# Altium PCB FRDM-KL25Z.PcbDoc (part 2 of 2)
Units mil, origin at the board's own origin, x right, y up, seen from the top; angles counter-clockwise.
Board outline 3200 x 2100 mil, 2 copper layers (Top Layer, Bottom Layer), stack 42.17 mil thick; 0 components, 164 nets, 466 pads, 402 vias.
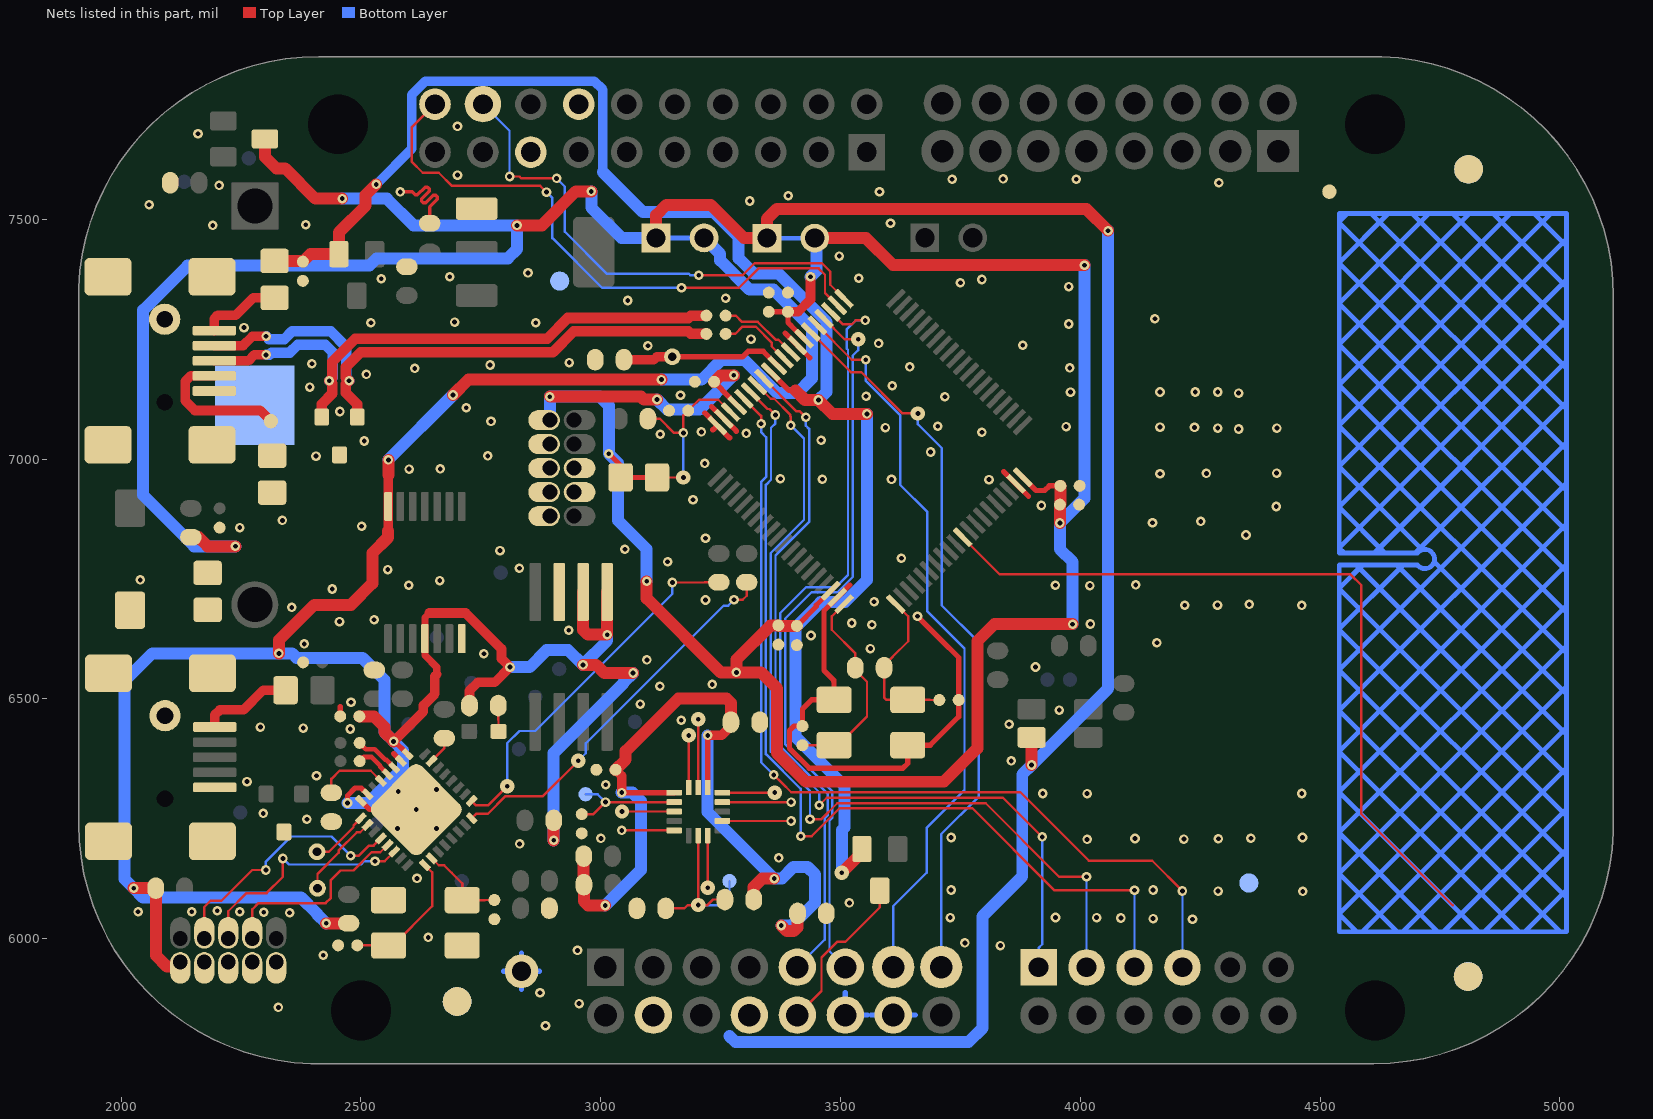
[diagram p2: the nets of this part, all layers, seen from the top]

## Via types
v1: diameter 20/20 (per signal layer), hole 10, Top Layer to Bottom Layer, 372 vias
v2: diameter 20/30 (per signal layer), hole 10, Top Layer to Bottom Layer, 25 vias
v3: diameter 20/30.04 (per signal layer), hole 10, Top Layer to Bottom Layer, 5 vias

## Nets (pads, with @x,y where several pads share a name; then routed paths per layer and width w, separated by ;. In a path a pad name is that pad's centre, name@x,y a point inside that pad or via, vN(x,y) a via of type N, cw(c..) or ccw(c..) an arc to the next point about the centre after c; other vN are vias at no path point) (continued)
$Net110: pad.6@2223.5,6000 pad.14@2569.57,6181.28 | length 486.1
  Top Layer w5: pad.6@2223.5,6001 2223.5,6057 2261.5,6095 2303.5,6095 2337.5,6129 v1(2337.5,6167) ; v1(2529.5,6161.5) 2549.79,6161.5 pad.14@2569.57,6181.28
  Bottom Layer w5: v1(2337.5,6167) 2349.88,6154.62 2359.88,6154.62 2359.97,6154.53 2500.03,6154.53 2507,6161.5 v1(2529.5,6161.5)
$Net111: pad.4@2173.5,6000 pad.12@2541.71,6209.14 | length 535.9
  Top Layer w5: pad.4@2173.5,6001 2173.5,6066 2186.5,6079 2209.5,6079 2273.5,6143 v1(2302,6143) ; v1(2478.5,6173) 2496,6173 2516.94,6193.94 2526.51,6193.94 pad.12@2541.71,6209.14
  Bottom Layer w5: v1(2302,6143) 2302,6160.5 2354.5,6213 2438.5,6213 v1(2478.5,6173)
$Net112: pad.1@2418.5,7087.5 pad.1@3220.5,7299 pad.3@2194.4,7204.8 | length 1279
  Top Layer w20: pad.3@2194.4,7204.8 2265.3,7204.8 2277.5,7217 v1(2302.5,7217)
  Top Layer w22: pad.1@2418.5,7087.5 2418.5,7114.56 2440.5,7136.56 2440.5,7156.48 v1(2433.98,7163) 2440.5,7169.52 2440.5,7203 2488.5,7251 2888.5,7251 2931.5,7294 3183,7294 3188,7299 pad.1@3220.5,7299
  Bottom Layer w22: v1(2302.5,7217) 2309.43,7217 2314.43,7222 2352.1,7222 2368.1,7238 2425.5,7238 2441.06,7222.44 2441.06,7170.08 v1(2433.98,7163)
$Net113: pad.1@2492.5,7087.5 pad.1@3220.5,7261 pad.2@2194.4,7236.3 | length 1283.4
  Top Layer w20: pad.2@2194.4,7236.3 2254.4,7236.3 2274.03,7255.93 v1(2302.5,7255.93)
  Top Layer w22: pad.1@2492.5,7087.5 2492.5,7114.56 2468.5,7138.56 2468.5,7156 v1(2475.5,7163) 2468.5,7170 2468.5,7191.4 2500.1,7223 2900.5,7223 2943.5,7266 3183,7266 3188,7261 pad.1@3220.5,7261
  Bottom Layer w22: v1(2302.5,7255.93) 2308.43,7250 2340.5,7250 2356.5,7266 2437.1,7266 2469.06,7234.04 2469.06,7169.44 v1(2475.5,7163)
$Net114: pad.1@3304.5,6743 pad.24@2731.08,6250.93 | length 805.6
  Top Layer w5: pad.24@2731.08,6250.93 2740.27,6260.12 2764.47,6260.12 2801.55,6297.2 2879.6,6297.2 v2(2953.1,6370.7) ; v1(3278,6706.5) 3296,6706.5 3304.5,6715 pad.1@3304.5,6743
  Bottom Layer w5: v2(2953.1,6370.7) 2969.01,6386.61 2969.01,6407.03 3256.1,6694.12 3265.62,6694.12 v1(3278,6706.5)
$Net115: pad.1@3246.5,6743 pad.25@2731.08,6287.07 | length 778.2
  Top Layer w5: pad.25@2731.08,6287.07 2740.27,6277.88 2765.38,6277.88 v2(2805,6317.5) ; v1(3149.5,6742.5) 3216,6742.5 3216.5,6743 pad.1@3246.5,6743
  Bottom Layer w5: v2(2805,6317.5) 2805,6407.2 2830.8,6433 2863.5,6433 3149.5,6719 v1(3149.5,6742.5)
$Net116: pad.1@2960.5,6259.5 pad.1@2968.5,6301 pad.2@3153.3,6284.69 | length 251.5
  Top Layer w5: pad.1@2960.5,6259.5 2984.85,6259.5 v1(3010.04,6284.69) pad.2@3153.3,6284.69
  Bottom Layer w5: pad.1@2968.5,6301 2993.73,6301 v1(3010.04,6284.69)
$Net117: pad.1@3135.5,6063 pad.1@3259,6081.5 pad.1@3268.5,6120 pad.7@3203.5,6214.8 | length 379.2
  Top Layer w5: pad.1@3135.5,6063 3174.4,6063 3181.4,6070 v2(3203.5,6070) ; pad.7@3203.5,6214.8 v2(3203.5,6070) ; pad.1@3259,6081.5 3234,6081.5 3222.5,6070 v2(3203.5,6070)
  Bottom Layer w5: v2(3203.5,6070) 3248.5,6070 3268.5,6090 pad.1@3268.5,6120
$Net118: pad.1@3223.19,6106.26 pad.8@3223.19,6214.8 | length 108.5
  Top Layer w5: v3(3223.19,6106.26) pad.8@3223.19,6214.8
$Net119: pad.1@3044.5,6265 pad.3@3153.3,6265 | length 108.8
  Top Layer w5: v3(3044.5,6265) pad.3@3153.3,6265
$Net120: pad.1@3183.81,6423.74 pad.16@3183.81,6315.2 | length 108.5
  Top Layer w5: pad.16@3183.81,6315.2 v3(3183.81,6423.74)
$Net121: pad.1@3203.5,6457.4 pad.15@3203.5,6315.2 | length 142.2
  Top Layer w5: pad.15@3203.5,6315.2 v3(3203.5,6457.4)
$Net122: pad.1@3363.11,6304.37 pad.13@3253.7,6304.37 | length 109.4
  Top Layer w5: pad.13@3253.7,6304.37 v3(3363.11,6304.37)
$Net123: pad.1@2409.5,6105 pad.10@2513.85,6237 | length 179.4
  Top Layer w5: pad.1@2409.5,6105 2409.5,6135 2453.5,6179 2453.5,6183.7 2491.6,6221.8 2498.65,6221.8 pad.10@2513.85,6237
$Net124: pad.1@2408.5,6181 pad.9@2499.92,6250.93 | length 122.4
  Top Layer w5: pad.1@2408.5,6181 2433.5,6181 2484.72,6232.22 2484.72,6235.73 pad.9@2499.92,6250.93
$Net126: pad.15@2854.5,7640
$Net127: pad.1@3582,6100.2 pad.12@3410.04,5840.65 | length 340.9
  Top Layer w5: pad.12@3410.04,5840.65 3460.5,5891.11 3460.5,5961 3492.7,5993.2 3510,5993.2 3582,6065.2 pad.1@3582,6100.2
$Net128: pad.1@2091.85,6464.81
$Net129: pad.1@2091.85,6291.59
$Net130: pad.1@2091.05,7291.41
$Net131: pad.1@2091.05,7118.19
$Net132: pad.1@2500,5850
$Net133: pad.1@2452,7698
$Net134: pad.1@4614.5,5850
$Net135: pad.1@4614.5,7698
$Net136: pad.1@2180.5,6685.5 pad.B01@1973.74,6203 pad.B01@1973.74,6553.4 pad.B01@2190.28,6203 pad.B01@2190.28,6553.4
$Net137: pad.1@2315,7007 pad.B01@1972.94,7029.6 pad.B01@1972.94,7380 pad.B01@2189.48,7029.6 pad.B01@2189.48,7380
$Net138: pad.1@2194.4,7267.79 pad.1@2320,7336 | length 168.5
  Top Layer w20: pad.1@2194.4,7267.79 2194.4,7292.79 2201.5,7299.89 2239.39,7299.89 2275.5,7336 pad.1@2320,7336
$Net139: pad.1@2786.5,6486 pad.1@2787.01,6432 | length 54.2
  Top Layer w5: pad.1@2786.5,6486 2786.5,6456 2787.01,6455.49 pad.1@2787.01,6432
$Net140: pad.1@3591,6564.8 pad.1@3640.17,6497.84 pad.1@3706.3,6497.5 pad.41 | length 343.7
  Top Layer w5: pad.41@3615.45,6697.58 3641.26,6671.77 3641.26,6620.16 3608.68,6587.58 3608.68,6587.48 3591,6569.8 pad.1@3591,6564.8 3591,6503.01 3596.17,6497.84 pad.1@3640.17,6497.84 3685.96,6497.84 3686.3,6497.5 pad.1@3706.3,6497.5
$Net141: pad.1@3420.7,6403.3 pad.1@3531,6564.8 pad.3@3486.63,6403.36 pad.40 | length 435.1
  Top Layer w5: pad.1@3420.7,6403.3 3442.57,6403.3 3442.63,6403.36 pad.3@3486.63,6403.36 3495.63,6403.36 3555.3,6463.03 3555.3,6535.5 3531,6559.8 pad.1@3531,6564.8 3531,6594.8 3481.74,6644.06 3481.74,6671.77 pad.40@3507.55,6697.58
$Net142: pad.1@2674.1,6417.9 pad.31@2647.5,6370.65 | length 58.3
  Top Layer w5: pad.31@2647.5,6370.65 2674.1,6397.25 pad.1@2674.1,6417.9
$Net143: pad.1@2195.2,6441.19 pad.1@2343,6518 | length 194.3
  Top Layer w20: pad.1@2195.2,6441.19 2195.2,6466.19 2205.91,6476.9 2255.4,6476.9 2296.5,6518 pad.1@2343,6518
$Net144: pad.1@2711.27,6080.24 pad.1@2778.5,6080.5 pad.18@2647.5,6167.35 | length 187.7
  Top Layer w5: pad.18@2647.5,6167.35 2648.15,6167.35 2662.5,6153 2673.5,6153 2689.5,6137 2711.27,6115.24 pad.1@2711.27,6080.24 2758.24,6080.24 2758.5,6080.5 pad.1@2778.5,6080.5
$Net145: pad.1@2492.5,5986 pad.3@2557.73,5985.76 pad.17@2633.57,6153.42 | length 282.3
  Top Layer w5: pad.1@2492.5,5986 2557.49,5986 pad.3@2557.73,5985.76 2566.73,5985.76 2648.77,6067.8 2648.77,6138.22 pad.17@2633.57,6153.42
$Net146: pad.8@2273.5,6000 pad.13@2555.64,6195.21 | length 419.4
  Top Layer w5: pad.8@2273.5,6001 2273.5,6061 2286.5,6074 2426.5,6074 2437.5,6085 2437.5,6122 2457.5,6142 2484.5,6142 2522.51,6180.01 2540.44,6180.01 pad.13@2555.64,6195.21
$Net147: pad.1@2497.5,6408 pad.3@2569.57,6356.72 | length 93.3
  Top Layer w10: pad.1@2497.5,6408 2510.5,6395 2528.5,6395 2550.5,6373 2553.29,6373 pad.3@2569.57,6356.72
$Net148: pad.1@2497.5,6370 pad.4@2555.64,6342.79 | length 78.3
  Top Layer w10: pad.1@2497.5,6370 2506.5,6379 2521.87,6379 2540.5,6360.37 2540.5,6357.93 pad.4@2555.64,6342.79
$Net151: pad.1@2312.5,7079 pad.4@2194.4,7173.3 | length 302.5
  Top Layer w20: pad.4@2194.4,7173.3 2145,7173.3 2133.5,7161.8 2133.5,7121.62 2153.92,7101.2 2290.3,7101.2 pad.1@2312.5,7079
$Net152: pad.51 | length 1619.1
  Top Layer w5: pad.51@3754.65,6836.77 3831.92,6759.5 4563.2,6759.5 4585.7,6737 4585.7,6260.1 4776.5,6069.3
$Net153: pad.1@2438.5,6304 pad.5@2541.71,6328.86 | length 147.9
  Top Layer w5: pad.1@2438.5,6304 2438.5,6333 2455.4,6349.9 2520.67,6349.9 pad.5@2541.71,6328.86
$Net154: 
$Net155: pad.9@2323.5,5951
$Net156: pad.7@2273.5,5951
$Net157: pad.9@2894,6881
$Net158: pad.8@2944,6931
$Net159: 
$Net160: pad.6@2944,6981
$Net161: 
$Net162: pad.1@2700.7,5868.9
$Net163: pad.1@4808.5,5921
$Net164: pad.1@4809.5,7604
$Net165: 
$Net166: 
$Net167: 
$Net168: 
$Net169: 
$Net170: 
$Net171: 
$Net172: 
$Net173: 
$Net174: pad.7@2894,6931
$Net175: 
$Net176: 
$Net177: pad.1@2700.7,5868.9
$Net178: pad.1@4808.7,5921.1
$Net179: pad.1@4809.5,7604.1
D14: pad.1@2754.5,7740 pad.1@3507.55,7334.42 | length 1068.9
  Top Layer w5: v1(2810,7589) 2830.5,7589 2834.5,7585 v1(2908,7585) ; v1(3204.5,7383) 3296,7383 3321,7408 3461.5,7408 3478.5,7391 3478.5,7363.47 pad.1@3507.55,7334.42
  Bottom Layer w5: pad.1@2754.5,7740 2810,7684.5 v1(2810,7589) ; v1(2908,7585) 2925.3,7567.7 2925.3,7473.7 3013,7386 3184,7386 3187,7383 v1(3204.5,7383)
D15: pad.2@3493.62,7320.5 pad.18@2654.5,7740 | length 1256
  Top Layer w5: pad.18@2654.5,7740 2606.5,7692 2606.5,7619.5 2629,7597 2662.5,7597 2690,7569.5 2874,7569.5 v1(2887,7556.5) ; v1(3168.5,7357) 3288.5,7357 3329,7397.5 3454.5,7397.5 3467.81,7384.19 3467.81,7346.31 pad.2@3493.62,7320.5
  Bottom Layer w5: v1(2887,7556.5) 2899.38,7544.12 2899.38,7460.62 3003,7357 v1(3168.5,7357)
GND: pad.1@2018.5,6684.7 pad.1@2102.5,7576 pad.1@2180.5,6762.5 pad.1@2205.5,6857 pad.1@2279,7111.95 pad.1@2315,6930 pad.1@2339.5,6222.5 pad.1@2379,7371.5 pad.1@2379.5,6576 pad.1@2438.5,6244 pad.1@2452.5,5986 pad.1@2455.5,7008.5 pad.1@2457,6463.5 pad.1@2528,6560 pad.1@2596,7401 pad.1@2615.5,6269 pad.1@2643.5,7491.5 pad.1@2741.45,7522.05 pad.1@2778.5,6040.5 pad.1@2835.1,5932 pad.1@2893,6063.5 pad.1@2914.5,7371 pad.1@2960.5,6219.5 pad.1@2988.5,7207 pad.1@2991,6352 pad.1@3075.5,6063 pad.1@3142.5,7101 pad.1@3196.5,7161 pad.1@3331.5,6451.5 pad.1@3350.5,7347 pad.1@3370.5,6613 pad.1@3390.5,7347 pad.1@3409,6612 pad.1@3420.7,6443.3 pad.1@3470.5,6052.5 pad.1@3746.3,6497.5 pad.1@3997.5,6905 pad.1@3998.5,6944 pad.1@4351.5,6116 pad.1@4519.4,7557.4 pad.2@2557.73,6080.24 pad.2@2583.5,6370.65 pad.2@3486.63,6497.84 pad.3@2173.5,5951 pad.3@2894,7031 pad.4@2711.27,5985.76 pad.4@3640.17,6403.36 pad.5@2194.4,7141.81 pad.5@2195.2,6315.21 pad.5@2223.5,5951 pad.5@2894,6981 pad.5@3153.3,6225.63 pad.7@2710.24,6625.5 pad.7@2913.5,6722.79 pad.8@2499.92,6287.07 pad.8@3410.11,7236.99 pad.10@3253.7,6245.31 pad.12@3253.7,6284.69 pad.14@2954.5,7740 pad.14@3510.04,5840.69 pad.16@3610.04,5840.73 pad.19@3257,7083.88 pad.20@3243.08,7069.95 pad.39 pad.59 | length 30353.5
  Top Layer w5: v1(3043.89,6225.63) pad.5@3153.3,6225.63 ; pad.10@3253.7,6245.31 v1(3396.96,6245.31) ; pad.12@3253.7,6284.69 v1(3396.96,6284.69)
  Top Layer w7: v1(2582,7557) 2607,7557 2613.06,7550.94 2618.02,7550.94 2634.06,7566.98 2639.02,7566.98 2642.55,7563.45 2642.55,7558.49 2626.51,7542.45 2626.51,7537.49 2630.04,7533.96 2635,7533.96 2651.04,7550 2656,7550 2659.53,7546.47 2659.53,7541.51 2643.5,7525.48 pad.1@2643.5,7491.5
  Top Layer w11: pad.1@2457,6463.5 2457,6483.52 ; pad.8@2499.92,6287.07 2518,6269 v1(2615.5,6269) ; 2568.28,6385.87 pad.2@2583.5,6370.65 ; 3217.26,7095.77 pad.20@3243.08,7069.95 ; 3231.18,7109.7 pad.19@3257,7083.88 3282.82,7058.06 ; 3233.87,7060.74 pad.20@3243.08,7069.95 ; 3268.9,7044.13 pad.20@3243.08,7069.95 ; 3384.29,7262.81 pad.8@3410.11,7236.99 3435.93,7211.17 ; 3519.44,6737.32 pad.39@3493.62,6711.5 3465.69,6683.57 3465.69,6559.21 3485.8,6539.1 3485.8,6536.67 3486.63,6535.84 pad.2@3486.63,6497.84 3439.63,6497.84 3420.7,6478.91 pad.1@3420.7,6443.3 3402.9,6443.3 3393.7,6434.1 3393.7,6396.7 3435,6355.4 3630.21,6355.4 3640.17,6365.36 pad.4@3640.17,6403.36 3687.17,6403.36 3746.3,6462.49 pad.1@3746.3,6497.5 3746.3,6521.5 3746.5,6521.7 3746.5,6586.1 3707.6,6625 3707.5,6625 v1(3660.5,6672) ; 3840.18,6973.94 pad.59@3866,6948.12 3891.82,6922.3
  Bottom Layer w10: 4540.01,6050.52 4576.03,6014.5 ; 4540,6051.74 5014,6525.74 ; 4540.01,6135.37 4660.88,6014.5 ; 4540.01,6136.6 5014,6610.59 ; 4540,6220.23 4745.73,6014.5 ; 4540.01,6221.45 5014,6695.44 ; 4540,6305.08 4830.58,6014.5 ; 4540,6306.3 5014,6780.3 ; 4540.01,6389.93 4915.44,6014.5 ; 4540,6391.15 5014,6865.15 ; 4540,6474.79 5000.29,6014.5 ; 4540.01,6476.01 5014,6950 ; 4540,6559.64 5014,6085.64 ; 4540.01,6560.86 5014,7034.85 ; 4540.01,6644.49 5014,6170.5 ; 4540,6645.71 4673.27,6778.98 ; 4540.01,6729.34 5014,6255.35 ; 4540.01,6730.57 4588.42,6778.98 ; 4540,6814.2 4550.18,6804.02 ; 4540.01,6815.42 5014,7289.41 ; 4540,6899.05 4635.03,6804.02 ; 4540,6900.27 5014,7374.27 ; 4540.01,6983.9 4713.12,6810.79 ; 4540,6985.12 5014,7459.12 ; 4540.01,7068.75 5014,6594.76 ; 4540.01,7069.98 4982.03,7512 ; 4540,7153.61 5014,6679.61 ; 4540.01,7154.83 4897.18,7512 ; 4540.01,7238.46 5014,6764.47 ; 4540,7239.68 4812.32,7512 ; 4540.01,7323.31 5014,6849.32 ; 4540.01,7324.54 4727.47,7512 ; 4540,7408.17 5014,6934.17 ; 4540.01,7409.39 4642.62,7512 ; 4540,7493.02 5014,7019.02 ; 4540,7494.24 4557.76,7512 ; 4575.22,6778.98 5014,6340.2 ; 4587.61,6014.5 5014,6440.89 ; 4605.88,7512 5014,7103.88 ; 4613.46,6804.02 5014,7204.56 ; 4660.07,6778.98 5014,6425.05 ; 4672.47,6014.5 5014,6356.03 ; 4690.73,7512 5014,7188.73 ; 4698.32,6804.03 5014,7119.71 ; 4737.79,6786.12 5014,6509.91 ; 4757.32,6014.5 5014,6271.18 ; 4775.58,7512 5014,7273.58 ; 4842.17,6014.5 5014,6186.33 ; 4860.44,7512 5014,7358.44 ; 4927.03,6014.5 5014,6101.47 ; 4945.29,7512 5014,7443.29 ; 5011.88,6014.5 5014,6016.62 ; 4540,6014.5 5014,6014.5 5014,7512 4540,7512 4540,6804.02 4702.87,6804.02 cw(c4718.5,6791.5) 4702.87,6778.98 4540,6778.98 4540,6014.5
  Bottom Layer w11: 2797.58,5932 pad.1@2835.1,5932 ; 2835.1,5894.48 pad.1@2835.1,5932 ; 2835.1,5969.52 pad.1@2835.1,5932 ; 2872.62,5932 pad.1@2835.1,5932 ; 3510.04,5887.21 pad.14@3510.04,5840.69 3556.56,5840.69 ; 3563.52,5840.73 pad.16@3610.04,5840.73 3656.56,5840.73
  other v1: 2885,5818.5 2328,5856.5 2955,5864.5 2873.5,5887 2421.5,5965.5 2951.7,5975.5 3833.5,5985.5 3759.5,5991 2640.5,6002.5 4233.9,6040.3 4151.8,6041.7 4084.7,6043.1 3728.7,6043.8 3948.4,6044.1 4034,6043.8 2351.5,6054 2297.5,6055 2035.5,6056 2147.5,6056 2247.5,6056 2200.5,6058 3518.7,6074.5 4287.3,6099.2 4464,6098.5 3730.7,6101.3 4151.8,6101.3 2617,6125.5 3371.1,6168.4 2831,6197.5 4014.1,6206.8 4216,6207.5 4288,6208.1 3000.5,6209 4114,6208.8 4355.8,6209.4 3730.7,6210.8 4463.3,6210.8 2576.1,6229.7 2657.7,6229.9 2387.5,6249 2296.5,6261 4014.1,6302.3 3921.8,6302.5 4461.9,6302.5 2577.9,6306.5 2657.6,6311 3010.4,6320.7 2262.5,6327.5 2407.5,6339.5 3856,6370.5 2478,6437 2380,6439 2290.5,6441 3851.5,6447 3168,6455.5 3956,6476.5 3082.5,6489 2479.5,6493 3123.5,6526 3232.8,6530.1 3906.63,6566.28 3096.4,6581.1 2756.6,6594.1 3562.3,6604.8 2382,6614.5 4159.7,6616.9 3438.5,6632 2933.3,6643 3565.5,6654.5 4021,6656 3523.5,6658 2455.5,6661 2527.5,6665 2356,6690.5 4218,6694.9 4286,6695.5 4461.9,6694.8 4352.4,6696.9 3570,6702.5 3218.5,6706 2440.5,6729 4020,6736 2600,6737 3948,6737 4115.5,6737.5 2664.3,6746.5 2040,6748 2556,6769.5 2830.5,6772.1 3139.5,6786 3627,6793 2790,6809 3050.5,6812 3218.5,6835 4345.5,6841.5 2247.5,6857 2501.5,6860 4150.5,6867 4251,6870 2336.5,6872 4408.5,6901 3919,6903 3192.5,6915 3606.4,6957.5 3809.6,6957 3462.4,6957.8 3374.8,6958.8 4166.2,6969.4 4263,6970 4409.2,6970.7 2600.5,6979 2665.4,6979.4 3216.8,6990.8 2406.5,7006 2764.5,7006.5 3687.9,7014.6 2507,7037.5 3459.5,7039 3124,7051.5 3303.5,7053.5 3794.9,7055.9 3210,7056.5 4330,7062.5 3593.7,7065.4 4286.5,7064.5 4409.9,7064.5 4238.1,7065.9 3970.5,7067.5 4166.2,7066.6 3702.9,7068.3 2771.4,7078.4 2456.3,7099 2719.8,7106.7 3717.8,7129.8 3553.4,7130.7 3166.5,7133 4330,7137.5 3979.5,7139.5 4166.2,7139.8 4239.5,7139.8 4286.7,7139.8 2393.5,7150 3608,7152.9 2511.5,7176.5 2612.5,7189 3978,7190 3644.5,7192 2769.5,7196 2398,7198.5 2934.5,7201 3098.5,7236 3880.2,7237.2 3579.5,7241 3313.5,7250 2256.4,7274.1 3976,7281.5 2521,7284 2864.5,7284 2695.5,7285.5 4155.5,7292.5 3056.5,7330.5 3260.5,7335 3976,7359.5 3750.1,7367.4 3794.9,7374.2 2542.5,7376 3538.1,7376.7 2685.5,7380 2848.5,7388 3497.5,7423 2191,7487 2385,7488.5 3604.2,7491.5 2058.5,7530 3311,7538 3391,7549 3581.4,7557.3 2204.5,7570.5 4289,7576 3732.7,7583.2 3991.7,7583.4 3839.1,7584 2701.5,7592 2160.5,7678 2701.5,7693.5
p3v3: pad.1@2072.4,6105.2 pad.1@2123.5,5951 pad.1@2145.5,6837 pad.1@2299.8,7667.5 pad.1@2474.5,6032 pad.1@2497,6463.5 pad.1@2597.43,6384.58 pad.1@2726.5,6486 pad.1@2894,7081 pad.1@2902,6246.5 pad.1@2964.5,6172 pad.1@2965,6112.5 pad.1@3031,6352 pad.1@3041.5,6961.5 pad.1@3098.5,7084 pad.1@3115.5,7461 pad.1@3117.5,6961.5 pad.1@3153.3,6304.37 pad.1@3182.5,7101 pad.1@3236.5,7161 pad.1@3271.5,6451.5 pad.1@3319,6081.5 pad.1@3346.5,7460.5 pad.1@3350.5,7307 pad.1@3370.5,6653 pad.1@3390.5,7307 pad.1@3409,6652 pad.1@3410.5,6052.5 pad.1@3957.5,6905 pad.1@3958.5,6944 pad.2@3215.5,7461 pad.2@3446.5,7460.5 pad.2@3898.44,6419.47 pad.4@2633.47,6625.5 pad.4@3110.04,5840.54 pad.5@3013.5,6722.79 pad.6@2963.5,6722.79 pad.7@2513.85,6301 pad.7@3424.03,7250.91 pad.10@3310.04,5840.62 pad.14@2556.7,6901.1 pad.14@3223.19,6315.2 pad.17@3284.84,7111.71 pad.18@3270.91,7097.79 pad.38 pad.60 | length 19383.3
  Top Layer w5: pad.1@3098.5,7084 3123.5,7084 3153,7054.5 v1(3172.5,7054.5) 3172.5,7091 pad.1@3182.5,7101 3205.1,7123.6 3245.1,7123.6 pad.18@3270.91,7097.79 ; pad.1@3117.5,6961.5 v2(3172.5,6961.5)
  Top Layer w10: pad.1@3041.5,6961.5 pad.1@3117.5,6961.5
  Top Layer w11: v1(2472.1,6282.7) 2472.1,6298 2488,6313.9 2500.6,6313.9 2513.5,6301 pad.7@2513.85,6301 ; v1(2568.31,6411.3) 2568.31,6413.7 pad.1@2597.43,6384.58 ; v1(3017,7011) 3042,6986 3042,6962 pad.1@3041.5,6961.5 ; v1(3043.89,6304.37) pad.1@3153.3,6304.37 ; pad.14@3223.19,6315.2 v1(3223.19,6423.74) ; pad.1@3236.5,7161 3252.77,7144.73 3252.77,7143.78 pad.17@3284.84,7111.71 ; pad.1@3350.5,7307 pad.1@3390.5,7307 3390.5,7284.5 3396.1,7278.9 3396.1,7278.84 pad.7@3424.03,7250.91 ; pad.1@3409,6652 3449.5,6692.5 3449.5,6695.2 pad.38@3479.71,6725.41 ; pad.60@3879.92,6962.05 3907.85,6934.12 3925.62,6934.12 3935.5,6944 pad.1@3958.5,6944
  Top Layer w15: 2643,6678.9 2633.47,6669.37 pad.4@2633.47,6625.5 2633.47,6590.63 2658.2,6565.9 2658.2,6551
  Top Layer w20: 2556.7,6849.5 pad.14@2556.7,6901.1 2556.7,6965.5 2557.4,6966.2 ; v1(2568.31,6411.3) 2630.4,6473.39 2630.4,6486.3 2654.4,6510.3 2654.4,6547.2 2658.2,6551 ; 2643,6678.9 2718.3,6678.9 2793.22,6603.98 2793.22,6583.78 v1(2810.9,6566.1) 2779.3,6534.5 2744,6534.5 2726.5,6517 pad.1@2726.5,6486 ; pad.1@3031,6352 3043.89,6339.11 v1(3043.89,6304.37) ; v1(3223.19,6423.74) 3252.24,6423.74 3271.5,6443 pad.1@3271.5,6451.5 ; pad.1@3390.5,7307 3412,7307 3437.5,7332.5 v1(3437.5,7380)
  Top Layer w25: v1(2026.4,6105.2) pad.1@2072.4,6105.2 2072.4,5965 2095.6,5941.8 2114.3,5941.8 pad.1@2123.5,5951 ; pad.1@2145.5,6837 2161.5,6837 2180.5,6818 v1(2238.5,6818) ; pad.1@2299.8,7667.5 2299.8,7630 2323.8,7606 2342,7606 2405,7543 v1(2461,7543) ; v1(2329.1,6594.7) 2329.1,6622.2 2402.95,6696.05 2479.35,6696.05 2524.1,6740.8 2524.1,6803.7 2556.7,6836.3 2556.7,6849.5 ; v1(2427.8,6032) pad.1@2474.5,6032 ; pad.1@2497,6463.5 2527,6463.5 2548.86,6441.64 2548.86,6430.75 v1(2568.31,6411.3) ; 2557.4,6966.2 v1(2557.4,6998.2) ; v1(2692.1,7133.5) 2724.1,7165.5 v1(3126.6,7165.5) ; v1(2825.5,7487) 2877.2,7487 2948.2,7558 v1(2980.5,7558) ; v1(2894,7130) 3084,7130 3090,7124 v1(3117.5,7124) ; v1(2902,6205.1) pad.1@2902,6246.5 ; v1(2963.1,6570.7) 2990.6,6570.7 3007.5,6553.8 v1(3067.5,6553.8) ; pad.6@2963.5,6722.79 2963.5,6643.5 2973.4,6633.6 v1(3013.5,6633.6) pad.5@3013.5,6722.79 ; pad.1@2964.5,6172 2964.5,6113 pad.1@2965,6112.5 2965,6078 2974.07,6068.93 3009.43,6068.93 v1(3009.5,6069) ; pad.1@3031,6352 3052.22,6373.22 3052.22,6390.72 3161.75,6500.25 3262.75,6500.25 3271.5,6491.5 pad.1@3271.5,6451.5 ; v1(3096,6745) 3096,6709.5 3250.5,6555 v1(3283,6555) ; pad.1@3115.5,7461 3115.5,7508.5 3137,7530 3229.5,7530 3299,7460.5 pad.1@3346.5,7460.5 3346.5,7500.5 3367.2,7521.2 4012.8,7521.2 v1(4058,7476) ; pad.1@3236.5,7161 3250,7174.5 v1(3277.5,7174.5) ; pad.1@3319,6081.5 3319,6107.7 3336.4,6125.1 v1(3361.7,6125.1) ; v1(3376.5,6027.3) 3388.3,6015.5 3402.5,6015.5 3410.5,6023.5 pad.1@3410.5,6052.5 ; pad.1@3409,6652 3371.5,6652 pad.1@3370.5,6653 3354.4,6653 3283,6581.6 v1(3283,6555) ; pad.2@3446.5,7460.5 3553.3,7460.5 3609.7,7404.1 v1(4008.8,7404.1) ; v1(3898.44,6362) pad.2@3898.44,6419.47 ; v1(3957.5,6866.5) pad.1@3957.5,6905 3958.5,6906 pad.1@3958.5,6944 ; v1(3984,6655.5) 3820.7,6655.5 3785.3,6620.1 3785.3,6396.8 3715.6,6327.1 3427.6,6327.1 3367.7,6387 3367.7,6521.8 3334.5,6555 v1(3283,6555)
  Bottom Layer w5: v2(3172.5,6961.5) v1(3172.5,7054.5)
  Bottom Layer w10: pad.1@3115.5,7461 pad.2@3215.5,7461 ; pad.1@3346.5,7460.5 pad.2@3446.5,7460.5
  Bottom Layer w25: v1(2238.5,6818) 2152.5,6818 2046,6924.5 2046,7310.3 2138.7,7403 2517.5,7403 2533,7418.5 2806.5,7418.5 2825.5,7437.5 v1(2825.5,7487) 2610,7487 2554,7543 v1(2461,7543) ; v1(2427.8,6032) 2408.35,6051.45 2408.35,6052.55 2375.15,6085.75 2045.85,6085.75 v1(2026.4,6105.2) 2006.95,6124.65 2006.95,6536.55 2065.1,6594.7 v1(2329.1,6594.7) 2356.6,6594.7 2366.1,6585.2 2503.3,6585.2 2548.86,6539.64 2548.86,6430.75 v1(2568.31,6411.3) 2587.76,6391.85 2587.76,6355.36 2515.1,6282.7 v1(2472.1,6282.7) ; v1(2557.4,6998.2) 2557.4,6998.8 v1(2692.1,7133.5) ; v1(2810.9,6566.1) 2851.8,6566.1 2887.1,6601.4 2932.4,6601.4 v1(2963.1,6570.7) 3013.5,6621.1 v1(3013.5,6633.6) ; pad.1@2894,7081 v1(2894,7130) 2998.5,7130 3017,7111.5 v1(3017,7011) 3036.45,6991.55 3036.45,6871.55 3096,6812 v1(3096,6745) ; v1(2902,6205.1) 2902,6387 3048.05,6533.05 3048.05,6534.35 v1(3067.5,6553.8) ; v1(2980.5,7558) 2980.5,7524 3043.5,7461 pad.1@3115.5,7461 ; v1(3009.5,6069) 3084,6143.5 3084,6286.5 3066.13,6304.37 v1(3043.89,6304.37) ; v1(3117.5,7124) 3138.5,7103 3206,7103 v1(3277.5,7174.5) ; v1(3126.6,7165.5) 3210.6,7165.5 3251.95,7206.85 3299.25,7206.85 3368.6,7137.5 3409.8,7137.5 3440.2,7167.9 3440.2,7273.1 3359.9,7353.4 3309.9,7353.4 3249.09,7414.21 3249.09,7427.41 pad.2@3215.5,7461 ; v1(3223.19,6423.74) 3223.19,6263.61 v1(3361.7,6125.1) 3377.6,6125.1 3401.9,6149.4 3431.2,6149.4 3447,6133.6 3447,6075.6 3398.7,6027.3 v1(3376.5,6027.3) ; 3268.68,5796.73 3281.25,5784.15 3766.65,5784.15 3796,5813.5 3796,6046.5 3878.99,6129.49 3878.99,6342.55 v1(3898.44,6362) 4058,6521.56 v1(4058,7476) ; v1(3437.5,7380) 3450,7392.5 3450,7457 pad.2@3446.5,7460.5 ; v1(3984,6655.5) 3984,6785.5 3957.5,6812 v1(3957.5,6866.5) 4008.8,6917.8 v1(4008.8,7404.1)
P5V_KL25Z: pad.1@2320,7413 pad.1@2379,7411.5 pad.1@2454.1,7427.3 pad.1@3544.6,6186.8 pad.12@3354.43,7181.31 | length 3312.7
  Top Layer w11: pad.12@3354.43,7181.31 3392.74,7143 3406,7143
  Top Layer w25: pad.1@2320,7413 2377.5,7413 pad.1@2379,7411.5 2394.8,7427.3 pad.1@2454.1,7427.3 2454.1,7472.3 2510.1,7528.3 2510.1,7550.6 v1(2532,7572.5) ; 3406,7143 3426,7123 v1(3454,7123) 3483,7094 v1(3555,7094) ; v2(3502.8,6137.5) 3544.6,6179.3 pad.1@3544.6,6186.8
  Bottom Layer w20: v1(2532,7572.5) 2606.5,7647 2606.5,7759.89 2634.61,7788 2986.5,7788 3004.5,7770 3004.5,7598.5
  Bottom Layer w25: 3004.5,7598.5 3088,7515 3235.5,7515 3287.5,7463 3287.5,7418.5 3319,7387 3370,7387 3471,7286 3471,7140 v1(3454,7123) ; v2(3502.8,6137.5) 3502.8,6226.3 3507.9,6231.4 3507.9,6319.1 3406.5,6420.5 3406.5,6649.5 3458.5,6701.5 3509,6701.5 3555,6747.5 v1(3555,7094)
PTE2: pad.3@3479.71,7306.59 pad.9@3410,5940.65 | length 1624.3
  Top Layer w5: pad.3@3479.71,7306.59 3505.52,7280.78 3523.46,7280.78 3531.68,7289 v1(3551.5,7289)
  Bottom Layer w5: pad.9@3410,5940.65 3467,5997.65 3467,6250.5 3473.16,6256.66 3473.16,6302.84 3374.5,6401.5 3374.5,6679 3428.5,6733 3490.5,6733 3515.6,6758.1 3515.6,7227.8 3513.4,7230 3513.4,7270.72 3531.68,7289 v1(3551.5,7289)
PTE3: pad.4@3465.79,7292.66 pad.11@3510,5940.69 | length 1549.8
  Top Layer w5: pad.4@3465.79,7292.66 3508.95,7249.5 v2(3537,7249.5)
  Bottom Layer w5: pad.11@3510,5940.69 3477.1,5973.57 3477.1,6246.45 3483.16,6252.51 3483.16,6306.99 3384.5,6405.65 3384.5,6667 3440,6722.5 3494.15,6722.5 3525.6,6753.95 3525.6,7215.6 3537,7227 v2(3537,7249.5)
PTE4: pad.5@3451.87,7278.75 pad.13@3610,5940.73 | length 1543.5
  Top Layer w5: pad.5@3451.87,7278.75 3523.62,7207 v1(3552.5,7207)
  Bottom Layer w5: v1(3552.5,7207) 3552.5,7163.5 3624.4,7091.6 3624.4,6946.35 3681.18,6889.57 3681.18,6682.16 3758.5,6604.84 3758.5,6309.8 3679.6,6230.9 3679.6,6137.35 3609.98,6067.73 3609.98,5987.23 pad.13@3610,5940.73
PTE5: pad.6@3437.95,7264.82 pad.15@3710,5940.77 | length 1533.2
  Top Layer w5: pad.6@3437.95,7264.82 3521.77,7181 3543.65,7181 3629.65,7095 v2(3661.5,7095)
  Bottom Layer w5: v2(3661.5,7095) 3661.5,7072.5 3711.18,7022.82 3711.18,6694.61 3788.5,6617.29 3788.5,6296.4 3710,6217.9 pad.15@3710,5940.77
PTE20: pad.1@3913,5940 pad.13@3340.51,7167.39 | length 1779.7
  Top Layer w5: pad.13@3340.51,7167.39 3408.55,7099.35 3415.52,7099.35 v1(3427.9,7086.97) ; v1(3455.66,6278.03) 3471.43,6293.8 3838.5,6293.8 v1(3920.7,6212.2)
  Bottom Layer w5: v1(3427.9,7086.97) 3427.9,7069.47 3434.5,7062.87 3434.5,6869 3364.5,6799 3364.5,6396.5 3455.66,6305.34 v1(3455.66,6278.03) ; pad.1@3913,5940 3913,5980.5 3920.7,5988.2 v1(3920.7,6212.2)
PTE21: pad.3@4013,5940 pad.14@3326.59,7153.47 | length 1854.9
  Top Layer w5: pad.14@3326.59,7153.47 3354.56,7125.5 3362,7125.5 3395,7092.5 3395,7089 3396.5,7087.5 v1(3396.5,7070) ; v1(3436.5,6248.73) 3459.73,6248.73 3493.1,6282.1 3802.8,6282.1 3955.8,6129.1 v1(4013,6129.1)
  Bottom Layer w5: v1(3396.5,7070) 3423.9,7042.6 3423.9,6873.52 3354.5,6804.12 3354.5,6389.8 3436.5,6307.8 v1(3436.5,6248.73) ; pad.3@4013,5940 v1(4013,6129.1)
PTE22: pad.5@4113,5940 pad.15@3312.68,7139.55 | length 1939.7
  Top Layer w5: pad.15@3312.68,7139.55 3348,7104.23 3351.93,7104.23 v1(3364.31,7091.85) ; v1(3417,6213.5) 3439.75,6213.5 3498.05,6271.8 3775.3,6271.8 3946.4,6100.7 v1(4113,6100.7)
  Bottom Layer w5: v1(3364.31,7091.85) 3364.31,7074.35 3355.23,7065.27 3355.23,6956.73 3344.5,6946 3344.5,6384.69 3417,6312.19 v1(3417,6213.5) ; pad.5@4113,5940 v1(4113,6100.7)
PTE23: pad.7@4213,5940 pad.16@3298.75,7125.63 | length 1930.3
  Top Layer w5: pad.16@3298.75,7125.63 3334.5,7089.88 v1(3334.5,7073.5) ; v1(3360.99,6341.31) 3377.84,6324.48 3397.22,6305.1 3875.2,6305.1 4018,6162.3 4150,6162.3 v1(4213,6099.3)
  Bottom Layer w5: v1(3334.5,7073.5) 3334.5,7056 3345,7045.5 3345,6962.5 3334.5,6952 3334.5,6367.8 v1(3360.99,6341.31) ; pad.7@4213,5940 v1(4213,6099.3)
USB_DN: pad.1@3260.5,7261 pad.10@3382.27,7209.15 | length 160.3
  Top Layer w5: pad.1@3260.5,7261 3280.5,7261 3295.5,7276 3323.35,7276 3356.46,7242.89 3356.46,7234.96 pad.10@3382.27,7209.15
USB_DP: pad.1@3260.5,7299 pad.9@3396.19,7223.07 | length 167.1
  Top Layer w5: pad.1@3260.5,7299 3281.5,7299 3294.5,7286 3327.5,7286 3364.62,7248.88 3370.38,7248.88 pad.9@3396.19,7223.07
USB_VOUT33: pad.1@3048.5,7207 pad.1@3149.5,7213 pad.11@3368.35,7195.23 | length 339.2
  Top Layer w11: pad.1@3149.5,7213 3295.5,7213 3307,7224.5 3339,7224.5 pad.11@3368.35,7195.23 pad.11@3368.35,7195.23
  Top Layer w20: pad.1@3048.5,7207 3111,7207 3117,7213 pad.1@3149.5,7213
copper on no net: | length 40176.6
  Top Layer w6: 3333.8,4546.37 3368.8,4546.37 ; 3333.8,4711.37 3368.8,4711.37 ; 3333.8,4871.37 3368.8,4871.37 ; 3380.85,4714.7 3413.75,4777.7 ; 3380.85,4777.7 3413.75,4714.7 ; 3381.8,4546.37 3416.8,4546.37 ; 3381.8,4711.37 3416.8,4711.37 ; 3381.8,4871.37 3416.8,4871.37 ; 3429.8,4546.37 3464.8,4546.37 ; 3429.8,4711.37 3464.8,4711.37 ; 3429.8,4871.37 3464.8,4871.37
  Top Layer w10: 1453.8,4484.7 5453.8,4484.7 ; 1453.8,4784.7 1453.8,4984.7 5453.8,4984.7 ; 1953.8,4284.7 1953.8,4484.7 ; 3203.8,4984.7 3203.8,5284.7 ; 3208.8,4284.7 3208.8,4484.7 ; 3703.8,4284.7 3703.8,4484.7
  Top Layer w20: 1453.8,4284.7 1453.8,5284.7 5453.8,5284.7 5453.8,4284.7 1453.8,4284.7
  Bottom Layer w6: 3333.8,4546.37 3368.8,4546.37 ; 3333.8,4711.37 3368.8,4711.37 ; 3333.8,4871.37 3368.8,4871.37 ; 3380.85,4714.7 3413.75,4777.7 ; 3380.85,4777.7 3413.75,4714.7 ; 3381.8,4546.37 3416.8,4546.37 ; 3381.8,4711.37 3416.8,4711.37 ; 3381.8,4871.37 3416.8,4871.37 ; 3429.8,4546.37 3464.8,4546.37 ; 3429.8,4711.37 3464.8,4711.37 ; 3429.8,4871.37 3464.8,4871.37 ; 5052.5,6555.92 5087.5,6570.5 5052.5,6585.08 ; 5052.5,6601.83 5052.5,6625.17 5087.5,6625.17 5087.5,6601.83 ; 5052.5,6776.75 5052.5,6792.5 5067.67,6794.25 5065.33,6789 5064.75,6784.92 5065.33,6780.83 5067.67,6776.75 5070.58,6773.83 5075.25,6772.67 5079.92,6773.25 5084,6776.17 5086.33,6780.25 5087.5,6785.5 5086.92,6790.75 5085.17,6794.83 5082.25,6798.33 ; 5052.5,6819.75 5052.5,6835.5 5067.67,6837.25 5065.33,6832 5064.75,6827.92 5065.33,6823.83 5067.67,6819.75 5070.58,6816.83 5075.25,6815.67 5079.92,6816.25 5084,6819.17 5086.33,6823.25 5087.5,6828.5 5086.92,6833.75 5085.17,6837.83 5082.25,6841.33 ; 5052.5,6883.17 5052.5,6859.83 5061.25,6864.5 5067.67,6867.42 5073.5,6869.75 5079.92,6871.5 5087.5,6872.67 ; 5052.5,7055.17 5052.5,7031.83 5061.25,7036.5 5067.67,7039.42 5073.5,7041.75 5079.92,7043.5 5087.5,7044.67 ; 5056.58,6732.58 5053.67,6735.5 5052.5,6739.58 5053.08,6743.67 5056,6747.75 5060.08,6750.67 5064.17,6752.42 5071.75,6753.58 5077.58,6753 5082.83,6750.67 5086.33,6746.58 5087.5,6741.92 5086.33,6737.83 5083.42,6734.33 5079.92,6732 5076.42,6731.42 5072.33,6732 5068.83,6734.33 5066.5,6737.25 5065.33,6741.33 5066.5,6746 5068.83,6749.5 5072.92,6753.58 ; 5058.33,6925.58 5054.83,6922.08 5053.08,6918 5052.5,6913.33 5053.67,6907.5 5056.58,6903.42 5060.08,6902.25 5063.58,6902.83 5066.5,6905.17 5072.33,6916.83 5076.42,6922.08 5082.25,6925.58 5087.5,6926.75 5087.5,6902.25 ; 5059.5,7093.5 5052.5,7086.5 5087.5,7086.5 ; 5069.42,6611.17 5069.42,6625.17 ; 5070.58,6668.17 5070.58,6653.58 ; 5075.83,6949.92 5075.83,6965.08 ; 5087.5,6644.83 5070.58,6653.58 ; 5087.5,6668.17 5052.5,6668.17 5052.5,6653.58 5054.25,6648.92 5056.58,6646 5061.25,6644.83 5065.92,6646 5068.83,6649.5 5070.58,6653.58 ; 5087.5,7079.5 5087.5,7093.5 ; 5052.5,6485.67 5054.25,6481 5056.58,6477.5 5060.08,6474.58 5064.17,6472.25 5070,6471.67 5075.83,6472.25 5079.92,6474.58 5083.42,6477.5 5085.75,6481 5087.5,6485.67 5087.5,6497.33 5052.5,6497.33 5052.5,6485.67 ; 5052.5,7000.5 5053.67,6995.83 5056.58,6992.33 5060.08,6990 5064.75,6988.25 5070,6987.67 5075.25,6988.25 5079.92,6990 5083.42,6992.33 5086.33,6995.83 5087.5,7000.5 5086.33,7005.17 5083.42,7008.67 5079.92,7011 5075.25,7012.75 5070,7013.33 5064.75,7012.75 5060.08,7011 5056.58,7008.67 5053.67,7005.17 5052.5,7000.5
  Bottom Layer w10: 1453.8,4484.7 5453.8,4484.7 ; 1453.8,4784.7 1453.8,4984.7 5453.8,4984.7 ; 1953.8,4284.7 1953.8,4484.7 ; 3203.8,4984.7 3203.8,5284.7 ; 3208.8,4284.7 3208.8,4484.7 ; 3703.8,4284.7 3703.8,4484.7
  Bottom Layer w20: 1453.8,4284.7 1453.8,5284.7 5453.8,5284.7 5453.8,4284.7 1453.8,4284.7

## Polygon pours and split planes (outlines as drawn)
GND on Top Layer "T-MAIN-GND" (solid, remove dead copper, pour order 120): 1911.5,6239 1911.5,7339 cw(c2411.5,7339) 2411.5,7839 4611.5,7839 cw(c4611.5,7339) 5111.5,7339 5111.5,6239 cw(c4611.5,6239) 4611.5,5739 2411.5,5739 cw(c2411.5,6239)
no net on Top Layer "Top Layer-No Net 11" (solid, pour order 92): 94 vertices, not listed, extent 4744.98,7539.52 4874.02,7668.52
no net on Top Layer "Top Layer-No Net 10" (solid, pour order 90): 93 vertices, not listed, extent 4743.98,5856.52 4873.02,5985.52
no net on Top Layer "Top Layer-No Net 5" (solid, pour order 80): 93 vertices, not listed, extent 2636.18,5804.42 2765.22,5933.42
$Net137 on Top Layer "Top Layer-$Net137" (solid, pour order 8): 145 vertices, not listed, extent 1944,6927.5 2361,7427.5
$Net136 on Top Layer "Top Layer-$Net136" (solid, pour order 4): 212 vertices, not listed, extent 1962.75,6153.5 2281,6690.5
no net on Top Overlay (solid): 91 vertices, not listed, extent 4088.2,6499.74 4092.72,6504.26
no net on Top Overlay (solid): 91 vertices, not listed, extent 3984.24,6608.7 3988.76,6613.22
no net on Top Overlay (solid): 91 vertices, not listed, extent 3825.28,6567.74 3829.8,6572.26
no net on Top Overlay (solid): 91 vertices, not listed, extent 3558.74,6562.5 3563.26,6567.02
no net on Top Overlay (solid): 91 vertices, not listed, extent 3302.28,6770.74 3306.8,6775.26
no net on Top Overlay (solid): 91 vertices, not listed, extent 3244.28,6770.74 3248.8,6775.26
no net on Top Overlay (solid): 91 vertices, not listed, extent 3286.74,6079.2 3291.26,6083.72
no net on Top Overlay (solid): 91 vertices, not listed, extent 3066.24,7081.7 3070.76,7086.22
no net on Top Overlay (solid): 91 vertices, not listed, extent 2992.74,6110.28 2997.26,6114.8
no net on Top Overlay (solid): 91 vertices, not listed, extent 2992.24,6169.78 2996.76,6174.3
no net on Top Overlay (solid): 91 vertices, not listed, extent 2860.74,6061.28 2865.26,6065.8
no net on Top Overlay (solid): 91 vertices, not listed, extent 2860.74,6118.2 2865.26,6122.72
no net on Top Overlay (solid): 91 vertices, not listed, extent 2869.74,6244.28 2874.26,6248.8
no net on Top Overlay (solid): 91 vertices, not listed, extent 3103.24,6060.7 3107.76,6065.22
no net on Top Overlay (solid): 91 vertices, not listed, extent 2525.7,6527.74 2530.22,6532.26
no net on Top Overlay (solid): 91 vertices, not listed, extent 2754.24,6483.78 2758.76,6488.3
no net on Top Overlay (solid): 91 vertices, not listed, extent 2584.28,6527.74 2588.8,6532.26
no net on Top Overlay (solid): 91 vertices, not listed, extent 2671.8,6445.64 2676.32,6450.16
no net on Top Overlay (solid): 91 vertices, not listed, extent 2472.2,6059.74 2476.72,6064.26
no net on Top Overlay (solid): 91 vertices, not listed, extent 2143.2,6864.74 2147.72,6869.26
no net on Top Overlay (solid): 91 vertices, not listed, extent 2100.14,6102.98 2104.66,6107.5
no net on Bottom Overlay (solid): 70 vertices, not listed, extent 3948.26,7193.73 3994.25,7214.98
no net on Bottom Overlay (solid): 69 vertices, not listed, extent 3820.35,7193.73 3866.34,7214.98
no net on Bottom Overlay (solid): 102 vertices, not listed, extent 3469.39,7142.99 3512.07,7176.9
no net on Bottom Overlay (solid): 69 vertices, not listed, extent 3277.75,7193.73 3323.74,7214.98
no net on Bottom Overlay (solid): 315 vertices, not listed, extent 3916.27,7117.97 4032.42,7240.01
no net on Bottom Overlay (solid): 99 vertices, not listed, extent 4028.65,7121.09 4116.43,7237.23
no net on Bottom Overlay (solid): 97 vertices, not listed, extent 4102.31,7121.09 4187,7278.24
no net on Bottom Overlay (solid): 409 vertices, not listed, extent 3546.58,7117.96 3663.28,7240.02
no net on Bottom Overlay (solid): 446 vertices, not listed, extent 3663.38,7117.97 3791.24,7240.02
no net on Bottom Overlay (solid): 320 vertices, not listed, extent 3788.37,7117.97 3904.51,7240.01
no net on Bottom Overlay (solid): 359 vertices, not listed, extent 3429.98,7117.97 3546.13,7240.01
no net on Bottom Overlay (solid): 321 vertices, not listed, extent 3245.77,7117.97 3361.91,7240.01
p3v3 on Bottom Layer "B-p3v3" (solid, pour order 43): 3446.5,6071.5 3397.48,6071.5 3311.7,5985.72 3300.34,5985.72 3025.32,5985.72 3025.32,5746.49 3446.5,5746.49
GND on Bottom Layer "B-MAIN-GND" (solid, remove dead copper, pour order 147): 22 vertices, not listed, extent 1911.5,5739 5111.5,7839

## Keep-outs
Keep-Out Layer:
  lines w1: 1911.5,6239 ccw(c2411.5,6239) 2411.5,5739 4611.5,5739 ccw(c4611.5,6239) 5111.5,6239 5111.5,7339 ccw(c4611.5,7339) 4611.5,7839 2411.5,7839 ccw(c2411.5,7339) 1911.5,7339 1911.5,6239

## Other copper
Top Layer:
  region net $Net152: 4781.38,7386.16 4997.38,6017.16 4535.38,6017.16 4535.38,7449.16 4744.38,6124.16 4781.38,6124.16
  region net $Net77: 4762.24,6138.36 4546.24,7507.36 5008.24,7507.36 5008.24,6075.36 4799.24,7400.36 4762.24,7400.36
  text "Imported into Altium Designer by Darren Moore" at 3352.6,5164.28 h60
  text "FREESCALE  SEMICONDUCTOR" at 1483,5160 h140
  text "6501  WILLIAM  CANNON  DRIVE  WEST" at 1486.22,5088.97 h80
  text "FRDM-KL25Z" at 3986.69,5040.34 h60
  text "AUSTIN.  TEXAS  78735  USA" at 1491,5016.11 h80
  text "PUBI (PUBLIC INFORMATION)" at 3529,4881 h82
  text "PROPRIETARY TO FREESCALE AND SHALL" at 1551.96,4832.1 h82
  text "NOT BE USED FOR ENGINEERING DESIGN" at 1554,4749 h82
  text "FIUO (FREESCALE INTERNAL USE ONLY)" at 3529,4722 h82
  text "PROCUREMENT OR MANUFACTURE IN WHOLE" at 1558,4673 h82
  text "OR IN PART WITHOUT THE CONSENT OF" at 1555,4590 h82
  text "FCP (FREESCALE CONFIDENTIAL PROPRIETARY)" at 3529,4557 h82
  text "FREESCALE." at 1569,4512 h82
  text "FILM" at 1988,4403 h80
  text "DATE" at 3240,4403 h80
  text "NUMBER" at 3738,4403 h80
  text "SHEET" at 1488,4402 h80
  text "170-27556 REV D" at 4090,4332 h120
  text "07-10-12" at 3258,4321 h80
  text "PRIMARY SILKSIDE" at 2094.02,4319.75 h110
  text "1 OF 8" at 1509,4317 h110
Bottom Layer:
  text "Imported into Altium Designer by Darren Moore" at 3352.6,5164.28 h60
  text "FREESCALE  SEMICONDUCTOR" at 1483,5160 h140
  text "6501  WILLIAM  CANNON  DRIVE  WEST" at 1486.22,5088.97 h80
  text "FRDM-KL25Z" at 3986.69,5040.34 h60
  text "AUSTIN.  TEXAS  78735  USA" at 1491,5016.11 h80
  text "PUBI (PUBLIC INFORMATION)" at 3529,4881 h82
  text "PROPRIETARY TO FREESCALE AND SHALL" at 1551.96,4832.1 h82
  text "NOT BE USED FOR ENGINEERING DESIGN" at 1554,4749 h82
  text "FIUO (FREESCALE INTERNAL USE ONLY)" at 3529,4722 h82
  text "PROCUREMENT OR MANUFACTURE IN WHOLE" at 1558,4673 h82
  text "OR IN PART WITHOUT THE CONSENT OF" at 1555,4590 h82
  text "FCP (FREESCALE CONFIDENTIAL PROPRIETARY)" at 3529,4557 h82
  text "FREESCALE." at 1569,4512 h82
  text "FILM" at 1988,4403 h80
  text "DATE" at 3240,4403 h80
  text "NUMBER" at 3738,4403 h80
  text "SHEET" at 1488,4402 h80
  text "170-27556 REV D" at 4090,4332 h120
  text "07-10-12" at 3258,4321 h80
  text "SECONDARY SIDE" at 2176,4320 h110
  text "2 OF 8" at 1509,4317 h110

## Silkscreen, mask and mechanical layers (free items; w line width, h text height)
Top Overlay:
  drawing of 12772 lines, arcs and shapes, not listed
  text "Imported into Altium Designer by Darren Moore" at 3352.6,5164.28 h60
  text "FREESCALE  SEMICONDUCTOR" at 1483,5160 h140
  text "6501  WILLIAM  CANNON  DRIVE  WEST" at 1486.22,5088.97 h80
  text "FRDM-KL25Z" at 3986.69,5040.34 h60
  text "AUSTIN.  TEXAS  78735  USA" at 1491,5016.11 h80
  text "PUBI (PUBLIC INFORMATION)" at 3529,4881 h82
  text "PROPRIETARY TO FREESCALE AND SHALL" at 1551.96,4832.1 h82
  text "NOT BE USED FOR ENGINEERING DESIGN" at 1554,4749 h82
  text "FIUO (FREESCALE INTERNAL USE ONLY)" at 3529,4722 h82
  text "PROCUREMENT OR MANUFACTURE IN WHOLE" at 1558,4673 h82
  text "OR IN PART WITHOUT THE CONSENT OF" at 1555,4590 h82
  text "FCP (FREESCALE CONFIDENTIAL PROPRIETARY)" at 3529,4557 h82
  text "FREESCALE." at 1569,4512 h82
  text "FILM" at 1988,4403 h80
  text "DATE" at 3240,4403 h80
  text "NUMBER" at 3738,4403 h80
  text "SHEET" at 1488,4402 h80
  text "170-27556 REV D" at 4090,4332 h120
  text "07-10-12" at 3258,4321 h80
  text "PRIMARY SILKSCREEN" at 2033,4320 h110
  text "5 OF 8" at 1509,4317 h110
Bottom Overlay:
  drawing of 11879 lines, arcs and shapes, not listed
  text "FREESCALE  SEMICONDUCTOR" at 1483,5160 h140
  text "6501  WILLIAM  CANNON  DRIVE  WEST" at 1486.22,5088.97 h80
  text "FRDM-KL25Z" at 4116.39,5069.16 h60
  text "AUSTIN.  TEXAS  78735  USA" at 1491,5016.11 h80
  text "PUBI (PUBLIC INFORMATION)" at 3529,4881 h82
  text "PROPRIETARY TO FREESCALE AND SHALL" at 1551.96,4832.1 h82
  text "NOT BE USED FOR ENGINEERING DESIGN" at 1554,4749 h82
  text "FIUO (FREESCALE INTERNAL USE ONLY)" at 3529,4722 h82
  text "PROCUREMENT OR MANUFACTURE IN WHOLE" at 1558,4673 h82
  text "OR IN PART WITHOUT THE CONSENT OF" at 1555,4590 h82
  text "FCP (FREESCALE CONFIDENTIAL PROPRIETARY)" at 3529,4557 h82
  text "FREESCALE." at 1569,4512 h82
  text "FILM" at 1988,4403 h80
  text "DATE" at 3240,4403 h80
  text "NUMBER" at 3738,4403 h80
  text "SHEET" at 1488,4402 h80
  text "170-27556 REV D" at 4090,4332 h120
  text "07-10-12" at 3258,4321 h80
  text "SECONDARY SILKSCREEN" at 1961,4320 h110
  text "8 OF 8" at 1509,4317 h110
Top Solder:
  region: 4313.01,6507.66 4248.18,6468.56 4208.79,6489.3 4273.12,6528.28
  region: 4372.47,6476.57 4307.64,6437.46 4268.26,6458.2 4332.58,6497.19
  region: 4283.58,6422.97 4218.75,6383.86 4179.36,6404.61 4243.69,6443.59
  region: 4224.33,6453.97 4159.5,6414.86 4120.11,6435.6 4184.44,6474.59
  region: 4194.83,6369.35 4130,6330.25 4090.61,6350.99 4154.94,6389.98
  region: 4401.81,6560.8 4336.98,6521.69 4297.59,6542.43 4361.92,6581.42
  region: 4342.45,6591.84 4277.62,6552.73 4238.23,6573.47 4302.56,6612.46
  region: 4283,6622.79 4243.11,6643.41 4178.79,6604.42 4218.17,6583.68
Mechanical 1:
  lines w1: 1911.5,6239 ccw(c2411.5,6239) 2411.5,5739 4611.5,5739 ccw(c4611.5,6239) 5111.5,6239 5111.5,7339 ccw(c4611.5,7339) 4611.5,7839 2411.5,7839 ccw(c2411.5,7339) 1911.5,7339 1911.5,6239 ; 4534.5,6010.66 4534.5,7517.5 5018.5,7517.5 5018.5,6010.66 4534.5,6010.66
  lines w6: 3333.8,4546.37 3368.8,4546.37 ; 3333.8,4711.37 3368.8,4711.37 ; 3333.8,4871.37 3368.8,4871.37 ; 3380.85,4714.7 3413.75,4777.7 ; 3380.85,4777.7 3413.75,4714.7 ; 3381.8,4546.37 3416.8,4546.37 ; 3381.8,4711.37 3416.8,4711.37 ; 3381.8,4871.37 3416.8,4871.37 ; 3429.8,4546.37 3464.8,4546.37 ; 3429.8,4711.37 3464.8,4711.37 ; 3429.8,4871.37 3464.8,4871.37
  lines w10: 1453.8,4484.7 5453.8,4484.7 ; 1453.8,4784.7 1453.8,4984.7 5453.8,4984.7 ; 1953.8,4284.7 1953.8,4484.7 ; 3203.8,4984.7 3203.8,5284.7 ; 3208.8,4284.7 3208.8,4484.7 ; 3703.8,4284.7 3703.8,4484.7
  lines w20: 1453.8,4284.7 1453.8,5284.7 5453.8,5284.7 5453.8,4284.7 1453.8,4284.7
  text "Imported into Altium Designer by Darren Moore" at 3352.6,5164.28 h60
  text "FREESCALE  SEMICONDUCTOR" at 1483,5160 h140
  text "6501  WILLIAM  CANNON  DRIVE  WEST" at 1486.22,5088.97 h80
  text "FRDM-KL25Z" at 3986.69,5040.34 h60
  text "AUSTIN.  TEXAS  78735  USA" at 1491,5016.11 h80
  text "PUBI (PUBLIC INFORMATION)" at 3529,4881 h82
  text "PROPRIETARY TO FREESCALE AND SHALL" at 1551.96,4832.1 h82
  text "NOT BE USED FOR ENGINEERING DESIGN" at 1554,4749 h82
  text "FIUO (FREESCALE INTERNAL USE ONLY)" at 3529,4722 h82
  text "PROCUREMENT OR MANUFACTURE IN WHOLE" at 1558,4673 h82
  text "OR IN PART WITHOUT THE CONSENT OF" at 1555,4590 h82
  text "FCP (FREESCALE CONFIDENTIAL PROPRIETARY)" at 3529,4557 h82
  text "FREESCALE." at 1569,4512 h82
  text "FILM" at 1988,4403 h80
  text "DATE" at 3240,4403 h80
  text "NUMBER" at 3738,4403 h80
  text "SHEET" at 1488,4402 h80
  text "170-27556 REV D" at 4090,4332 h120
  text "07-10-12" at 3258,4321 h80
  text "SECONDARY PASTEMASK" at 1986,4320 h110
  text "7 OF 8" at 1509,4317 h110
Mechanical 2:
  drawing of 29540 lines, arcs and shapes, not listed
